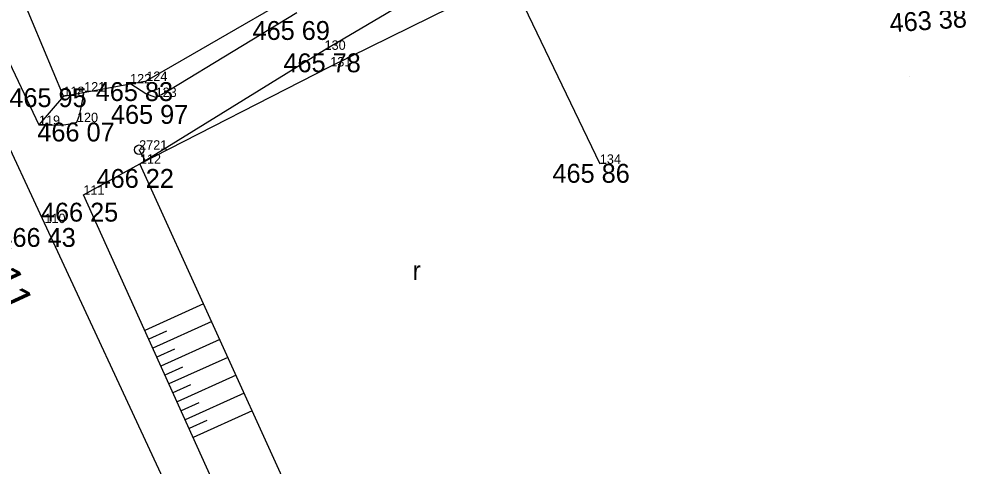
# Model space of a CAD drawing. Extents: x -559180 to -551373, y -1076947 to -1072071.
# Drawn here: x -553890.3 to -553840.2, y -1075298.9 to -1075275.2 of the extents above; entities that cross this region are included whole.
import ezdxf

# ---------------------------------------------------------------- set-up
doc = ezdxf.new("R2010")
doc.units = 0
for name, color, linetype in [('12_PLOTY', 7, 'Continuous'), ('17_KOMUNIKACE', 7, 'Continuous'), ('1_VODA_ZN', 7, 'Continuous'), ('24_KULTURA', 7, 'Continuous'), ('26_SRAFY', 7, 'Continuous'), ('27_HRANA_PATA', 7, 'Continuous'), ('2_VODOVOD', 7, 'Continuous'), ('3_BODY', 7, 'Continuous'), ('45_ZN_KULTURY', 7, 'Continuous'), ('52_POPIS_UCELOVY', 7, 'Continuous'), ('6_VYSKY', 7, 'Continuous')]:
    doc.layers.add(name, color=color, linetype=linetype)

# ---------------------------------------------------------------- blocks, each defined once
blk = doc.blocks.new('ROLE')
at = {"layer": '45_ZN_KULTURY'}
blk.add_text('r', height=1, dxfattribs=at).set_placement((0, 0.048))
blk = doc.blocks.new('SV')
at = {"layer": '1_VODA_ZN'}
blk.add_circle((0, 0), 0.25, dxfattribs=at)
blk = doc.blocks.new('POINT_DISPLAY')
blk.add_line((0, 0), (0, 0))

msp = doc.modelspace()

# ---------------------------------------------------------------- linework, layer by layer
at = {"layer": '12_PLOTY'}
for p, q in [((-553887.97, -1075279.31), (-553895, -1075262.39)), ((-553875.99, -1075274.11), (-553883.58, -1075278.51)), ((-553887.97, -1075279.31), (-553883.58, -1075278.51))]:
    msp.add_line(p, q, dxfattribs=at)
at = {"layer": '17_KOMUNIKACE'}
for p, q in [((-553888.97, -1075286.04), (-553902.95, -1075255.99)), ((-553883.92, -1075282.89), (-553874.15, -1075276.86)), ((-553886.91, -1075284.54), (-553883.92, -1075282.89)), ((-553867.21, -1075332.86), (-553888.97, -1075286.04))]:
    msp.add_line(p, q, dxfattribs=at)
for points in [[(-553874.15, -1075276.86), (-553868.619, -1075273.567), (-553867.536, -1075272.999), (-553866.83, -1075272.66)], [(-553883.09, -1075279.36), (-553882.78, -1075279.221), (-553882.347, -1075278.987), (-553875.62, -1075274.89)], [(-553884.407, -1075278.661), (-553883.599, -1075279.168), (-553883.284, -1075279.297), (-553883.09, -1075279.36)], [(-553887.25, -1075280.69), (-553887.134, -1075280.368), (-553887.055, -1075280.089), (-553886.952, -1075279.554), (-553886.877, -1075279.111)], [(-553889.26, -1075280.84), (-553888.614, -1075280.854), (-553888.108, -1075280.839), (-553887.842, -1075280.813), (-553887.625, -1075280.778), (-553887.25, -1075280.69)]]:
    msp.add_lwpolyline(points, dxfattribs=at)
at = {"layer": '24_KULTURA'}
for p, q in [((-553864.16, -1075273.36), (-553859.59, -1075282.9)), ((-553873.85, -1075277.74), (-553865.91, -1075273.82)), ((-553883.92, -1075282.89), (-553873.85, -1075277.74)), ((-553861.53, -1075332.24), (-553883.92, -1075282.89))]:
    msp.add_line(p, q, dxfattribs=at)
at = {"layer": '26_SRAFY'}
for p, q in [((-553880.552, -1075290.313), (-553883.667, -1075291.72)), ((-553880.123, -1075291.259), (-553883.24, -1075292.666)), ((-553882.519, -1075291.771), (-553883.453, -1075292.193)), ((-553879.694, -1075292.204), (-553882.812, -1075293.613)), ((-553882.091, -1075292.717), (-553883.026, -1075293.14)), ((-553879.265, -1075293.15), (-553882.385, -1075294.559)), ((-553881.663, -1075293.663), (-553882.598, -1075294.086)), ((-553878.836, -1075294.096), (-553881.957, -1075295.506)), ((-553881.235, -1075294.61), (-553882.171, -1075295.032)), ((-553878.407, -1075295.041), (-553881.53, -1075296.452)), ((-553880.807, -1075295.556), (-553881.743, -1075295.979)), ((-553877.978, -1075295.987), (-553881.102, -1075297.398)), ((-553880.379, -1075296.502), (-553881.316, -1075296.925))]:
    msp.add_line(p, q, dxfattribs=at)
at = {"layer": '27_HRANA_PATA'}
for p, q in [((-553901.45, -1075255.15), (-553889.26, -1075280.84)), ((-553887.97, -1075279.31), (-553889.26, -1075280.84)), ((-553865.04, -1075332.96), (-553886.91, -1075284.54))]:
    msp.add_line(p, q, dxfattribs=at)
at = {"layer": '2_VODOVOD'}
msp.add_line((-553883.638, -1075282.717), (-553883.96, -1075282.15), dxfattribs=at)

# ---------------------------------------------------------------- block references
at = {"layer": '1_VODA_ZN'}
for name, p in [('POINT_DISPLAY', (-553874.15, -1075276.86)), ('POINT_DISPLAY', (-553873.85, -1075277.74)), ('POINT_DISPLAY', (-553843.189, -1075278.254)), ('POINT_DISPLAY', (-553884.44, -1075278.64)), ('POINT_DISPLAY', (-553883.58, -1075278.51)), ('POINT_DISPLAY', (-553887.97, -1075279.31)), ('POINT_DISPLAY', (-553886.87, -1075279.07)), ('POINT_DISPLAY', (-553883.09, -1075279.36)), ('POINT_DISPLAY', (-553889.26, -1075280.84)), ('POINT_DISPLAY', (-553887.25, -1075280.69)), ('SV', (-553883.96, -1075282.15)), ('POINT_DISPLAY', (-553883.96, -1075282.15)), ('POINT_DISPLAY', (-553883.92, -1075282.89)), ('POINT_DISPLAY', (-553859.59, -1075282.9)), ('POINT_DISPLAY', (-553886.91, -1075284.54)), ('POINT_DISPLAY', (-553888.97, -1075286.04))]:
    msp.add_blockref(name, p, dxfattribs=at)
at = {"layer": '45_ZN_KULTURY'}
msp.add_blockref('ROLE', (-553869.5, -1075289.1), dxfattribs=at)

# ---------------------------------------------------------------- texts
at = {"layer": '3_BODY'}
for s, p in [('130', (-553874.15, -1075276.86)), ('131', (-553873.85, -1075277.74)), ('122', (-553884.44, -1075278.64)), ('124', (-553883.58, -1075278.51)), ('118', (-553887.97, -1075279.31)), ('121', (-553886.87, -1075279.07)), ('123', (-553883.09, -1075279.36)), ('119', (-553889.26, -1075280.84)), ('120', (-553887.25, -1075280.69)), ('2721', (-553883.96, -1075282.15)), ('112', (-553883.92, -1075282.89)), ('134', (-553859.59, -1075282.9)), ('111', (-553886.91, -1075284.54)), ('110', (-553888.97, -1075286.04))]:
    msp.add_text(s, height=0.5, dxfattribs=at).set_placement(p)
at = {"layer": '52_POPIS_UCELOVY'}
msp.add_text('státní silnice č.11', height=1.6, rotation=294.7006, dxfattribs=at).set_placement((-553897.811, -1075276.038))
at = {"layer": '6_VYSKY'}
msp.add_text('463 38', height=1, rotation=3.8499, dxfattribs=at).set_placement((-553844.229, -1075275.937))
for s, p in [('465 69', (-553877.961, -1075276.335)), ('465 78', (-553876.327, -1075278.048)), ('465 95', (-553890.826, -1075279.892)), ('465 83', (-553886.256, -1075279.572)), ('465 97', (-553885.453, -1075280.782)), ('466 07', (-553889.345, -1075281.713)), ('465 86', (-553862.095, -1075283.9)), ('466 22', (-553886.214, -1075284.171)), ('466 25', (-553889.157, -1075285.959)), ('466 43', (-553891.404, -1075287.298))]:
    msp.add_text(s, height=1, dxfattribs=at).set_placement(p)

doc.saveas('drawing.dxf')
